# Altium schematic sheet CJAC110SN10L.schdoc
size 127 x 101 mm
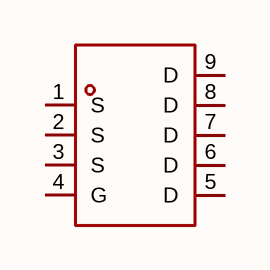
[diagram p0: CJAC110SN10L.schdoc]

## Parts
Q?  cjac110sn10l  [PDFN-8_L5.8-W4.9-P1.27-LS6.1-BL-A]  (value not drawn)

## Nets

Not connected (* = marked no-connect by the designer): Q? 1(S) 2(S) 3(S) 4(G) 5(D) 6(D) 7(D) 8(D) 9(D)

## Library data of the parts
Q? = cjac110sn10l: 数量:1个N沟道;漏源电压(Vdss):100V;连续漏极电流(Id):110A;导通电阻(RDS(on)):6mΩ@4.5V;耗散功率(Pd):130W;阈值电压(Vgs(th)):1.5V;; Manufacturer: CJ(江苏长电/长晶); AddInBom: yes; ModelId: 450a83d8ea544a1683b51becadb75d8a; ModelTransform: 200.787,238.189,0,0,0,0,-0.005,0.003,0; Number: 1个N沟道; Drain to Source Voltage: 100V; Current - Continuous Drain(Id): 110A; Pd - Power Dissipation: 130W; Gate Threshold Voltage (Vgs(th)): 1.5V; Gate Charge(Qg): 156nC@15V; Input Capacitance(Ciss): 3.366nF; Reverse Transfer Capacitance (Crss@Vds): 11pF; Type: N沟道; Output Capacitance(Coss): 657pF; Vgs: ±20V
